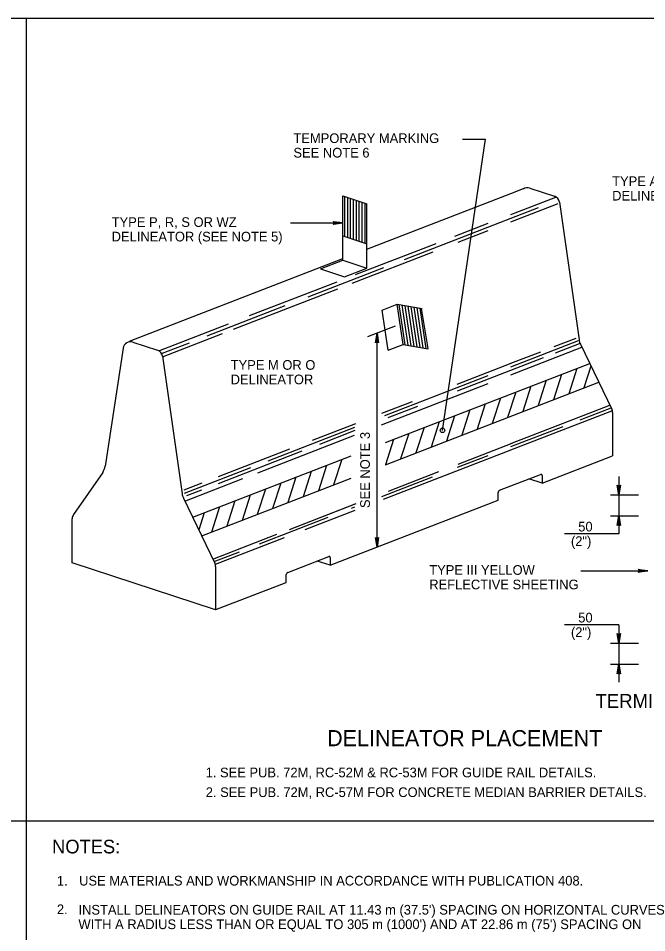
# Model space of a CAD drawing. Extents: x 640253 to 641999, y 298458 to 299646.
# Drawn here: x 640798.8 to 640993.9, y 298753 to 299036.6 of the extents above; entities that cross this region are included whole.
import ezdxf

# ---------------------------------------------------------------- set-up
doc = ezdxf.new("R2010")
doc.units = 0
doc.layers.add('1', color=7, linetype='Continuous')
doc.layers.add('2', color=7, linetype='Continuous')

msp = doc.modelspace()

# ---------------------------------------------------------------- linework, layer by layer
at = {"layer": '1'}
for p, q in [((640293.31, 299036.63), (641079.31, 299036.63)), ((640801.38, 298472.63), (640801.38, 299036.63)), ((640293.31, 298787.67), (641079.31, 298787.67))]:
    msp.add_line(p, q, dxfattribs=at)
at = {"layer": '2'}
for p, q in [((640930.48, 298908.79), (640943.83, 298999.15)), ((640936.73, 298999.15), (640943.83, 298999.15)), ((640951.73, 298982.3), (640956.11, 298984)), ((640957.62, 298983.95), (640965.2, 298981.46)), ((640899.54, 298961.59), (640899.54, 298981.54)), ((640899.54, 298981.54), (640907.03, 298979.08)), ((640900.15, 298968.95), (640900.15, 298981.34)), ((640901.05, 298968.66), (640901.05, 298981.04)), ((640901.95, 298968.36), (640901.95, 298980.75)), ((640907.03, 298965), (640951.73, 298982.3)), ((640951.73, 298975.77), (640965.71, 298981.18)), ((640902.85, 298968.07), (640902.85, 298980.45)), ((640903.75, 298967.77), (640903.75, 298980.16)), ((640904.65, 298967.47), (640904.65, 298979.86)), ((640905.55, 298967.18), (640905.55, 298979.57)), ((640906.45, 298966.89), (640906.45, 298979.27)), ((640907.03, 298959.13), (640907.03, 298979.08)), ((640918.67, 298961.77), (640960.33, 298977.89)), ((640951.73, 298973.49), (640966.43, 298979.19)), ((640966.81, 298979.57), (640972.89, 298936.9)), ((640883.31, 298973.12), (640899.54, 298973.12)), ((640934.34, 298969.05), (640944.63, 298973.03)), ((640899.54, 298969.15), (640907.03, 298966.7)), ((640935.32, 298967.14), (640944.63, 298970.75)), ((640903.5, 298957.11), (640928.55, 298966.8)), ((640902.44, 298954.42), (640927.55, 298964.14)), ((640833.28, 298936.45), (640899.54, 298962.1)), ((640892.6, 298958.9), (640899.54, 298961.59)), ((640899.54, 298961.59), (640907.03, 298959.13)), ((640888.78, 298950.2), (640912.25, 298959.29)), ((640892.6, 298958.9), (640900.09, 298956.45)), ((640900.09, 298956.45), (640907.03, 298959.13)), ((640865.65, 298940.18), (640897.97, 298952.69)), ((640870.62, 298944.4), (640897.74, 298954.86)), ((640857.44, 298938.14), (640881.63, 298947.51)), ((640911.77, 298946.1), (640916.42, 298947.9)), ((640918.23, 298935.45), (640916.42, 298947.9)), ((640916.42, 298947.9), (640924.18, 298946.55)), ((640918.86, 298935.34), (640917.05, 298947.8)), ((640919.79, 298935.18), (640917.98, 298947.63)), ((640920.73, 298935.01), (640918.92, 298947.47)), ((640921.66, 298934.85), (640919.85, 298947.31)), ((640922.59, 298934.69), (640920.78, 298947.14)), ((640923.53, 298934.53), (640921.72, 298946.98)), ((640924.46, 298934.36), (640922.65, 298946.82)), ((640925.39, 298934.2), (640923.58, 298946.65)), ((640926.07, 298934.14), (640924, 298946.55)), ((640913.58, 298933.64), (640911.77, 298946.1)), ((640842.48, 298933.48), (640864.06, 298941.84)), ((640907.33, 298937.88), (640915.87, 298941.19)), ((640843.59, 298931.63), (640862.22, 298938.84)), ((640910.16, 298872.55), (640910.16, 298938.98)), ((640834.4, 298936.2), (640841.97, 298933.71)), ((640843.3, 298932.64), (640851.92, 298935.99)), ((640913.58, 298933.64), (640918.23, 298935.45)), ((640918.23, 298935.45), (640926, 298934.1)), ((640951.73, 298928.54), (640972.74, 298936.66)), ((640965.17, 298934.8), (640972.01, 298937.43)), ((640965.56, 298932.85), (640972.98, 298935.73)), ((640973.31, 298935.51), (640983.05, 298915.35)), ((640831.35, 298934.32), (640825.77, 298897.72)), ((640951.73, 298926.06), (640973.75, 298934.58)), ((640951.73, 298929.6), (640961.03, 298933.2)), ((640843.56, 298931.81), (640849.66, 298889.14)), ((640912.75, 298904.98), (640976.19, 298929.55)), ((640935.08, 298923.15), (640951.84, 298929.63)), ((640951.73, 298927.5), (640961.88, 298931.43)), ((640935.13, 298921.08), (640951.73, 298927.51)), ((640972.18, 298928), (640969.66, 298920.15)), ((640976.57, 298928.75), (640974.4, 298921.99)), ((640912.6, 298913.39), (640944.63, 298925.78)), ((640912.75, 298898.11), (640978.99, 298923.76)), ((640962.69, 298924.32), (640960.17, 298916.48)), ((640967.44, 298926.16), (640964.91, 298918.31)), ((640911.52, 298910.51), (640944.63, 298923.33)), ((640957.95, 298922.49), (640955.43, 298914.64)), ((640948.47, 298918.81), (640945.95, 298910.97)), ((640953.21, 298920.65), (640950.69, 298912.8)), ((640911.68, 298914.09), (640921.19, 298917.78)), ((640913.67, 298912.78), (640922.86, 298916.32)), ((640943.73, 298916.98), (640941.2, 298909.13)), ((640951.73, 298904.7), (640982.45, 298916.56)), ((640973.21, 298912.07), (640982.82, 298915.81)), ((640934.24, 298913.3), (640931.72, 298905.46)), ((640938.98, 298915.14), (640936.46, 298907.29)), ((640951.73, 298902.74), (640983.05, 298914.87)), ((640983.29, 298914.32), (640983.29, 298900.86)), ((640876.42, 298899.37), (640903.32, 298909.79)), ((640890.15, 298905.75), (640903.6, 298910.96)), ((640924.76, 298909.63), (640922.23, 298901.78)), ((640929.5, 298911.47), (640926.98, 298903.62)), ((640951.73, 298903.77), (640967.93, 298910.04)), ((640873.14, 298895.63), (640903.14, 298907.25)), ((640892.41, 298904.56), (640903.4, 298908.81)), ((640920.01, 298907.79), (640917.49, 298899.95)), ((640915.27, 298905.96), (640912.75, 298898.11)), ((640935.37, 298898.34), (640952.1, 298904.81)), ((640860.9, 298894.44), (640883.13, 298903.03)), ((640860.95, 298892.35), (640886.96, 298902.42)), ((640912.16, 298887.44), (640951.99, 298902.87)), ((640852.95, 298881.82), (640902.12, 298900.87)), ((640899.22, 298899.74), (640896.7, 298891.89)), ((640935.16, 298897.37), (640944.63, 298901.03)), ((640961.42, 298892.38), (640983.29, 298900.86)), ((640825.01, 298895.75), (640815.96, 298882.72)), ((640850.38, 298889.29), (640871.03, 298897.3)), ((640889.74, 298896.07), (640887.22, 298888.22)), ((640894.48, 298897.9), (640891.96, 298890.06)), ((640913.72, 298889.96), (640929.3, 298895.99)), ((640850.45, 298886.85), (640868.5, 298893.85)), ((640855.75, 298876.03), (640902.12, 298893.99)), ((640885, 298894.23), (640882.47, 298886.38)), ((640911.7, 298888.29), (640927.37, 298894.35)), ((640961.42, 298892.38), (640957.3, 298893.74)), ((640985.22, 298894.44), (640985.22, 298876.68)), ((640850.34, 298890.33), (640855.91, 298892.49)), ((640851.13, 298888.56), (640855.81, 298890.38)), ((640875.51, 298890.56), (640872.99, 298882.71)), ((640880.25, 298892.39), (640877.73, 298884.55)), ((640961.42, 298892.39), (640961.42, 298892.39)), ((640850.08, 298887.75), (640859.83, 298867.6)), ((640866.03, 298886.88), (640863.51, 298879.04)), ((640870.77, 298888.72), (640868.25, 298880.87)), ((640895.65, 298866.93), (640947.76, 298887.1)), ((640982.63, 298888.75), (640991.3, 298888.75)), ((640861.29, 298885.05), (640858.76, 298877.2)), ((640882.95, 298878.05), (640903.7, 298886.08)), ((640882.95, 298878.05), (640903.35, 298885.95)), ((640902.25, 298884.65), (640903.23, 298885.02)), ((640815.54, 298867.73), (640815.54, 298881.38)), ((640856.54, 298883.21), (640854.84, 298877.91)), ((640873.7, 298873.59), (640894.99, 298881.83)), ((640887.9, 298878.04), (640903.35, 298884.03)), ((640982.63, 298882.25), (640991.3, 298882.25)), ((640859.22, 298868.86), (640879.09, 298876.55)), ((640985.22, 298876.68), (640968.31, 298876.68)), ((640860, 298867.24), (640881.4, 298875.52)), ((640859.58, 298868.1), (640867.42, 298871.15)), ((640860.06, 298853.07), (640815.54, 298867.73)), ((640895.65, 298866.93), (640891.57, 298868.26)), ((640860.06, 298866.57), (640860.06, 298853.07)), ((640973.4, 298865.2), (640994.25, 298865.2)), ((640860.12, 298853.17), (640881.99, 298861.64)), ((640881.99, 298861.64), (640881.99, 298861.64)), ((640985.22, 298848.44), (640968.31, 298848.44)), ((640985.22, 298848.44), (640985.22, 298830.68)), ((640982.63, 298842.75), (640991.3, 298842.75)), ((640982.63, 298836.25), (640991.3, 298836.25))]:
    msp.add_line(p, q, dxfattribs=at)
for points in [[(640896.69, 298973.48), (640896.79, 298973.28), (640899.54, 298973.12), (640896.69, 298973.48), (640896.54, 298973.61), (640899.54, 298973.12), (640896.8, 298972.99), (640896.7, 298972.79), (640899.54, 298973.12), (640896.54, 298972.65), (640896.7, 298972.79)], [(640909.8, 298936.12), (640910.01, 298936.23), (640910.16, 298938.98), (640909.8, 298936.12), (640909.68, 298935.98), (640910.16, 298938.98), (640910.3, 298936.23), (640910.5, 298936.13), (640910.16, 298938.98), (640910.64, 298935.98), (640910.5, 298936.13)], [(640948.23, 298890.19), (640960.93, 298895.13)], [(640961.42, 298894.78), (640961.42, 298892.38)], [(640985.58, 298891.6), (640985.37, 298891.49), (640985.22, 298888.75), (640985.58, 298891.6), (640985.7, 298891.75), (640985.22, 298888.75), (640985.08, 298891.49), (640984.88, 298891.59), (640985.22, 298888.75), (640984.74, 298891.75), (640984.88, 298891.59)], [(640947.76, 298887.11), (640947.76, 298889.51)], [(640984.86, 298879.39), (640985.06, 298879.5), (640985.22, 298882.25), (640984.86, 298879.39), (640984.73, 298879.25), (640985.22, 298882.25), (640985.35, 298879.5), (640985.56, 298879.4), (640985.22, 298882.25), (640985.69, 298879.25), (640985.56, 298879.4)], [(640910.52, 298875.4), (640910.31, 298875.3), (640910.16, 298872.55), (640910.52, 298875.4), (640910.64, 298875.55), (640910.16, 298872.55), (640910.03, 298875.29), (640909.82, 298875.39), (640910.16, 298872.55), (640909.68, 298875.55), (640909.82, 298875.39)], [(640882.46, 298864.73), (640895.16, 298869.66)], [(640895.65, 298869.32), (640895.65, 298866.93)], [(640991.4, 298865.56), (640991.5, 298865.35), (640994.25, 298865.2), (640991.4, 298865.56), (640991.25, 298865.69), (640994.25, 298865.2), (640991.51, 298865.07), (640991.41, 298864.86), (640994.25, 298865.2), (640991.25, 298864.73), (640991.41, 298864.86)], [(640881.99, 298861.64), (640881.99, 298864.04)], [(640985.58, 298845.6), (640985.37, 298845.49), (640985.22, 298842.75), (640985.58, 298845.6), (640985.7, 298845.75), (640985.22, 298842.75), (640985.08, 298845.49), (640984.88, 298845.59), (640985.22, 298842.75), (640984.74, 298845.75), (640984.88, 298845.59)], [(640984.86, 298833.39), (640985.06, 298833.5), (640985.22, 298836.25), (640984.86, 298833.39), (640984.73, 298833.25), (640985.22, 298836.25), (640985.35, 298833.5), (640985.56, 298833.4), (640985.22, 298836.25), (640985.69, 298833.25), (640985.56, 298833.4)]]:
    msp.add_lwpolyline(points, dxfattribs=at)
msp.add_circle((640930.48, 298908.79), 0.691, dxfattribs=at)
for centre, radius, start, end in [((640956.9, 298981.73), 2.34, 71.7735, 124.6618), ((640964.47, 298979.23), 2.34, 8.1301, 71.7736), ((640833.67, 298933.97), 2.34, 71.7735, 171.3546), ((640977.53, 298937.56), 4.69, 188.13, 205.8211), ((640841.24, 298931.48), 2.34, 8.1301, 71.7736), ((640980.95, 298914.34), 2.34, 0, 25.821), ((640821.15, 298898.43), 4.69, 325.2567, 351.3547), ((640961.06, 298894.79), 0.366, 0, 111.2452), ((640948.49, 298889.51), 0.732, 111.1757, 180), ((640854.3, 298889.81), 4.69, 188.13, 205.8211), ((640817.89, 298881.39), 2.34, 145.2568, 180), ((640857.72, 298866.59), 2.34, 0, 25.821), ((640895.29, 298869.32), 0.366, 0, 111.2554), ((640882.72, 298864.06), 0.732, 111.1757, 180)]:
    msp.add_arc(centre, radius, start, end, dxfattribs=at)

# ---------------------------------------------------------------- texts
for s, height, p in [('TEMPORARY MARKING', 3, (640884.21, 298997.93)), ('SEE NOTE 6', 3, (640884.21, 298993.43)), ('TYPE A or B', 3, (640983.15, 298984.59)), ('DELINEATOR', 3, (640983.15, 298980.09)), ('TYPE P, R, S OR WZ ', 3, (640827.79, 298971.9)), ('DELINEATOR (SEE NOTE 5)', 3, (640827.79, 298967.4)), ('TYPE M OR O', 3, (640864.73, 298927.59)), ('DELINEATOR', 3, (640864.73, 298923.09)), ('50', 3, (640972.62, 298877.43)), ('(2")', 3, (640970.36, 298872.93)), ('TYPE III YELLOW', 3, (640926.37, 298863.98)), ('REFLECTIVE SHEETING', 3, (640926.37, 298859.48)), ('50', 3, (640972.62, 298849.2)), ('(2")', 3, (640970.36, 298844.7)), ('TERMINAL SECTION DETAIL', 4.3, (640977.99, 298822.71)), ('DELINEATOR PLACEMENT', 5, (640894.66, 298810.81)), ('1. SEE PUB. 72M, RC-52M & RC-53M FOR GUIDE RAIL DETAILS.', 3, (640856.96, 298801.16)), ('2. SEE PUB. 72M, RC-57M FOR CONCRETE MEDIAN BARRIER DETAILS.', 3, (640857, 298795.04)), ('NOTES:', 4.25, (640809.29, 298777.55)), ('1.', 3, (640810.79, 298767.58)), ('USE MATERIALS AND WORKMANSHIP IN ACCORDANCE WITH PUBLICATION 408.', 3, (640817.69, 298767.59)), ('2.', 3, (640810.78, 298758.73)), ("INSTALL DELINEATORS ON GUIDE RAIL AT 11.43 m (37.5') SPACING ON HORIZONTAL CURVES", 3, (640817.48, 298758.57)), ("WITH A RADIUS LESS THAN OR EQUAL TO 305 m (1000') AND AT 22.86 m (75') SPACING ON", 3, (640817.48, 298754.07))]:
    msp.add_text(s, height=height, dxfattribs=at).set_placement(p)
msp.add_text('SEE NOTE 3', height=3, rotation=90, dxfattribs=at).set_placement((640907.94, 298884.68))

doc.saveas('drawing.dxf')
